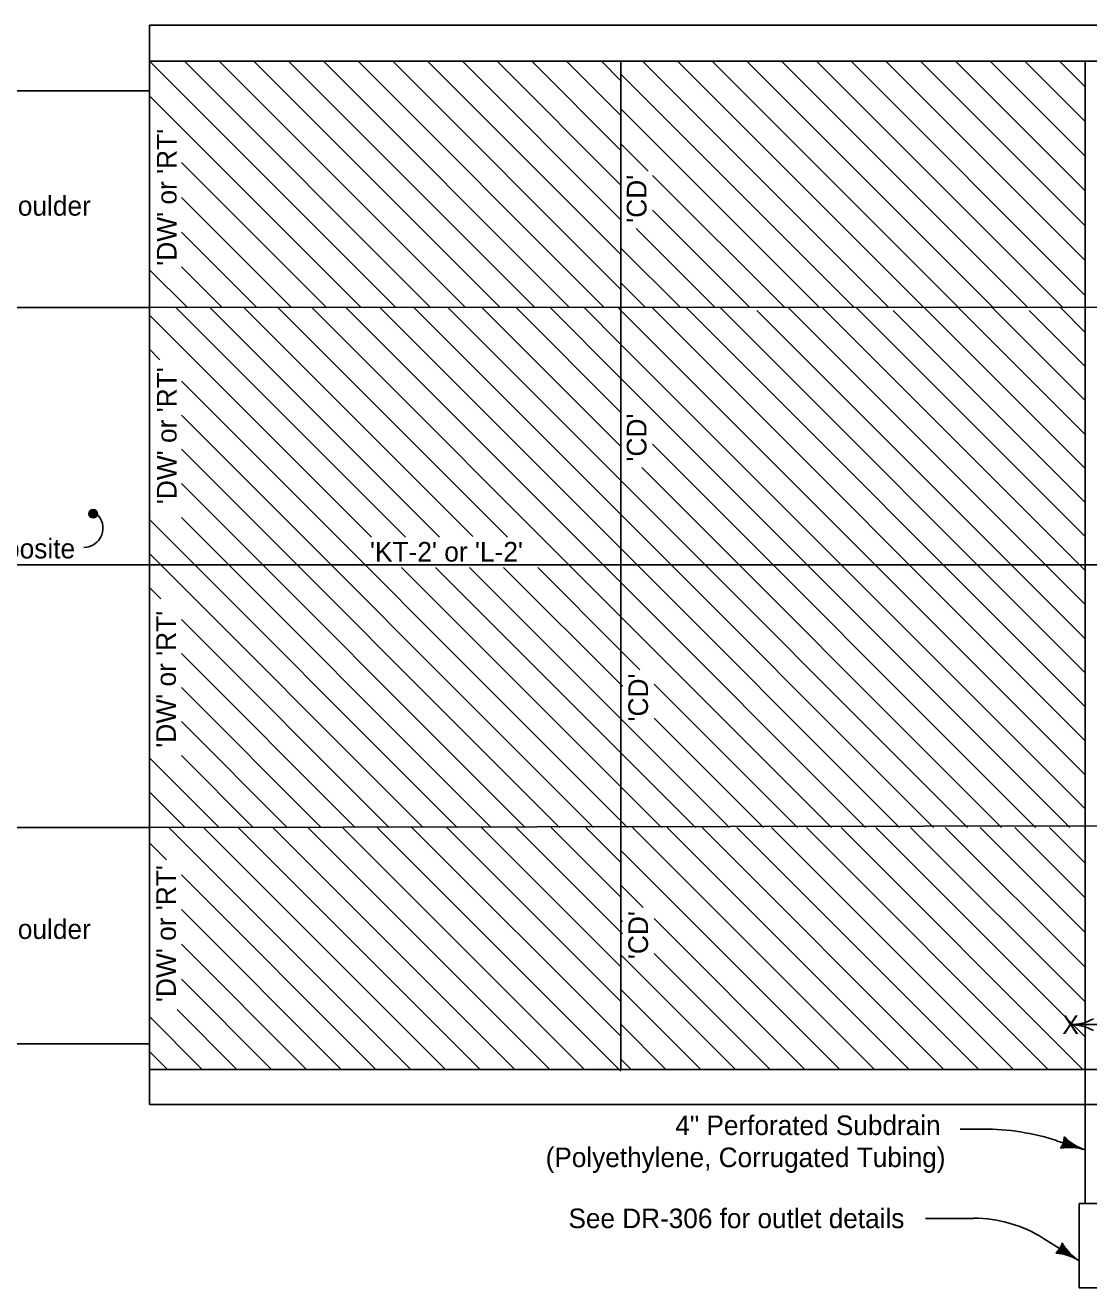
# Model space of a CAD drawing. Extents: x 9234 to 81668, y 5635 to 15999.
# Drawn here: x 24175 to 25088, y 5673 to 6757 of the extents above; entities that cross this region are included whole.
import ezdxf

# ---------------------------------------------------------------- set-up
doc = ezdxf.new("R2010")
doc.units = 0
doc.layers.add('PS_BOLT', color=7, linetype='Continuous')
doc.layers.add('PS_DIM', color=7, linetype='Continuous')

msp = doc.modelspace()

# ---------------------------------------------------------------- linework, layer by layer
msp.add_line((25828.3, 6726.2), (24281.5, 6726.2))
at = {"layer": 'PS_BOLT'}
for p, q in [((24281.5, 6562.1), (24281.5, 6603.8)), ((24281.5, 6514.6), (24281.5, 6068.3)), ((24750.3, 6068.3), (24686.4, 6132.3)), ((24721.1, 6068.3), (24686.4, 6103.1)), ((26267.5, 6071.6), (24281.5, 6068.3)), ((24691.9, 6068.3), (24686.4, 6073.9)), ((25072.2, 5898.9), (25103.5, 5898.9)), ((24977.8, 5809.2), (24997.5, 5809.2)), ((24947.8, 5732.6), (24989.3, 5732.6)), ((25049.4, 5715.4), (25079.9, 5696.2))]:
    msp.add_line(p, q, dxfattribs=at)
for centre, radius, start, end in [((24225, 6325.2), 16.5, 270, 48.6908), ((24997.5, 5603.7), 205.6, 72.1406, 90), ((24989.3, 5619.6), 113.1, 57.9168, 90)]:
    msp.add_arc(centre, radius, start, end, dxfattribs=at)
at = {"layer": 'PS_DIM'}
for p, q in [((26204.1, 6757), (24281.5, 6757)), ((24281.5, 6757), (24281.5, 6700.7)), ((24281.5, 6514.6), (24281.5, 6726.2)), ((24493.1, 6514.6), (24281.5, 6726.1)), ((24522.9, 6514.6), (24311.4, 6726.1)), ((24552.8, 6514.6), (24341.2, 6726.1)), ((24582.6, 6514.6), (24371.1, 6726.1)), ((24612.5, 6514.6), (24400.9, 6726.1)), ((24642.3, 6514.6), (24430.8, 6726.1)), ((24672.1, 6514.6), (24460.6, 6726.1)), ((24686.4, 6530.2), (24490.5, 6726.1)), ((24686.4, 6560.1), (24520.3, 6726.1)), ((24686.4, 6589.9), (24550.2, 6726.1)), ((24686.4, 6619.8), (24580, 6726.1)), ((24686.4, 6649.6), (24609.9, 6726.1)), ((24686.4, 6679.5), (24639.7, 6726.1)), ((24686.4, 6709.3), (24669.6, 6726.1)), ((24686.4, 6726.1), (24686.4, 6068.3)), ((24916.5, 6514.6), (24705, 6726.1)), ((24946.4, 6514.6), (24734.8, 6726.1)), ((24976.2, 6514.6), (24764.6, 6726.2)), ((25006.1, 6514.6), (24794.5, 6726.2)), ((25035.9, 6514.6), (24824.3, 6726.2)), ((25065.8, 6514.6), (24854.2, 6726.2)), ((25085.1, 6525.1), (24884, 6726.2)), ((25085.1, 6555), (24913.9, 6726.2)), ((25085.1, 6584.8), (24943.7, 6726.2)), ((25085.1, 6614.7), (24973.6, 6726.2)), ((25085.1, 6644.5), (25003.4, 6726.2)), ((25085.1, 6674.4), (25033.3, 6726.2)), ((25085.1, 6704.2), (25063.1, 6726.2)), ((25085.1, 6726.2), (25085.1, 6515.7)), ((24886.7, 6514.6), (24686.4, 6714.9)), ((24281.5, 6700.6), (24020.1, 6700.6)), ((24281.5, 6514.6), (24281.5, 6700.6)), ((25085.1, 6515.7), (25085.1, 6700.7)), ((24463.2, 6514.6), (24281.5, 6696.4)), ((24856.8, 6514.6), (24686.4, 6685.1)), ((24709.8, 6631.8), (24686.4, 6655.2)), ((24433.4, 6514.6), (24308.9, 6639.1)), ((24827, 6514.6), (24713.6, 6628)), ((24403.5, 6514.6), (24308.9, 6609.2)), ((24797.1, 6514.6), (24713.6, 6598.1)), ((24767.3, 6514.6), (24699.5, 6582.4)), ((24373.7, 6514.6), (24308.9, 6579.4)), ((24737.4, 6514.6), (24686.4, 6565.7)), ((24343.8, 6514.6), (24308.9, 6549.5)), ((24314, 6514.6), (24281.5, 6547.1)), ((24707.6, 6514.6), (24686.4, 6535.8)), ((24281.5, 6514.6), (26314.2, 6515.7)), ((25085.1, 6071.6), (25085.1, 6515.7)), ((24281.5, 6514.6), (23985.1, 6514.6)), ((24472, 6317.4), (24281.5, 6508)), ((24501.2, 6317.4), (24304.1, 6514.6)), ((24530.4, 6317.4), (24333.3, 6514.6)), ((24559.1, 6318), (24362.5, 6514.6)), ((24588.9, 6317.4), (24391.7, 6514.6)), ((24686.4, 6249.2), (24420.9, 6514.6)), ((24686.4, 6278.4), (24450.2, 6514.6)), ((24686.4, 6307.6), (24479.4, 6514.6)), ((24686.4, 6336.8), (24508.6, 6514.6)), ((24686.4, 6366.1), (24537.8, 6514.6)), ((24686.4, 6395.3), (24567, 6514.6)), ((24686.4, 6424.5), (24596.3, 6514.6)), ((24686.4, 6453.7), (24625.5, 6514.6)), ((24686.4, 6482.9), (24654.7, 6514.6)), ((24686.4, 6512.2), (24683.9, 6514.6)), ((25085.1, 6113.5), (24686.4, 6512.2)), ((25085.1, 6142.7), (24713.1, 6514.6)), ((25085.1, 6171.9), (24742.4, 6514.6)), ((25085.1, 6201.1), (24771.6, 6514.6)), ((25085.1, 6230.3), (24803.2, 6512.2)), ((25085.1, 6259.6), (24830, 6514.6)), ((25085.1, 6288.8), (24859.2, 6514.6)), ((25085.1, 6318), (24888.4, 6514.6)), ((25085.1, 6347.2), (24920.1, 6512.2)), ((25085.1, 6376.4), (24946.9, 6514.6)), ((25085.1, 6405.6), (24976.1, 6514.6)), ((25085.1, 6434.9), (25005.3, 6514.6)), ((25085.1, 6464.1), (25037, 6512.2)), ((25085.1, 6493.3), (25063.8, 6514.6)), ((25085.1, 6084.2), (24686.4, 6482.9)), ((24290.4, 6469.8), (24281.5, 6478.8)), ((24686.4, 6073.9), (24308.9, 6451.3)), ((25071.8, 6068.3), (24686.4, 6453.7)), ((24662.7, 6068.3), (24308.9, 6422.1)), ((24686.4, 6424.5), (24686.4, 6424.5)), ((25042.5, 6068.3), (24713.6, 6397.2)), ((24633.5, 6068.3), (24308.9, 6392.9)), ((24686.4, 6395.3), (24686.4, 6395.3)), ((25013.3, 6068.3), (24704.3, 6377.3)), ((24604.2, 6068.3), (24308.9, 6363.6)), ((24984.1, 6068.3), (24686.4, 6366.1)), ((24545.8, 6068.3), (24281.5, 6332.7)), ((24575, 6068.3), (24308.9, 6334.4)), ((24954.9, 6068.3), (24686.4, 6336.8)), ((24516.6, 6068.3), (24281.5, 6303.4)), ((24925.7, 6068.3), (24686.4, 6307.6)), ((25828.3, 6293.7), (23947.1, 6293.7)), ((24686.4, 6103.1), (24498, 6291.5)), ((24686.4, 6132.3), (24527.2, 6291.5)), ((24687.8, 6160.1), (24556.4, 6291.5)), ((24687.8, 6189.4), (24585.6, 6291.5)), ((24686.4, 6220), (24614.9, 6291.5)), ((24896.4, 6068.3), (24686.4, 6278.4)), ((24291.3, 6264.4), (24281.5, 6274.2)), ((24487.4, 6068.3), (24308.9, 6246.8)), ((24867.2, 6068.3), (24686.4, 6249.2)), ((24458.1, 6068.3), (24308.9, 6217.5)), ((24702.7, 6203.6), (24686.4, 6220)), ((24687.8, 6189.4), (24686.4, 6190.7)), ((24838, 6068.3), (24715, 6191.3)), ((24428.9, 6068.3), (24308.9, 6188.3)), ((24399.7, 6068.3), (24308.9, 6159.1)), ((24779.6, 6068.3), (24686.4, 6161.5)), ((24808.8, 6068.3), (24715, 6162.1)), ((24341.3, 6068.3), (24281.5, 6128.1)), ((24370.5, 6068.3), (24308.9, 6129.9)), ((24312, 6068.3), (24281.5, 6098.9)), ((25085.1, 6071.6), (25085.1, 5861.1)), ((24281.5, 6068.3), (23985.1, 6068.3)), ((24281.5, 5861.1), (24281.5, 6068.3)), ((24505.2, 5861.1), (24298, 6068.3)), ((24535, 5861.1), (24327.9, 6068.3)), ((24564.9, 5861.1), (24357.7, 6068.3)), ((24594.7, 5861.1), (24387.5, 6068.3)), ((24624.6, 5861.1), (24417.4, 6068.3)), ((24654.4, 5861.1), (24447.2, 6068.3)), ((24686.4, 5859), (24477.1, 6068.3)), ((24686.4, 5888.9), (24506.9, 6068.3)), ((24686.4, 5918.7), (24536.8, 6068.3)), ((24686.4, 5948.6), (24566.6, 6068.3)), ((24687.8, 5977), (24596.5, 6068.3)), ((24686.4, 6008.3), (24626.3, 6068.3)), ((24686.4, 6038.1), (24656.2, 6068.3)), ((24686.4, 6068.3), (24686.4, 5861.1)), ((24903.5, 5861.1), (24696.3, 6068.3)), ((24933.4, 5861.1), (24726.2, 6068.3)), ((24963.2, 5861.1), (24756, 6068.3)), ((24993.1, 5861.1), (24785.9, 6068.3)), ((25022.9, 5861.1), (24815.7, 6068.3)), ((25052.8, 5861.1), (24845.6, 6068.3)), ((25082.6, 5861.1), (24875.4, 6068.3)), ((25085.1, 5888.5), (24905.3, 6068.3)), ((25085.1, 5918.4), (24935.1, 6068.3)), ((25085.1, 5948.2), (24964.9, 6068.3)), ((25085.1, 5978.1), (24994.8, 6068.3)), ((25085.1, 6007.9), (25024.6, 6068.3)), ((25085.1, 6037.7), (25054.5, 6068.3)), ((24296.2, 6040.3), (24281.5, 6055)), ((24873.7, 5861.1), (24686.4, 6048.4)), ((24475.3, 5861.1), (24308.9, 6027.6)), ((24705.4, 5999.5), (24686.4, 6018.6)), ((24445.5, 5861.1), (24308.9, 5997.7)), ((24687.8, 5987.4), (24686.4, 5988.8)), ((24843.8, 5861.1), (24715, 5990)), ((24415.7, 5861.1), (24308.9, 5967.9)), ((24784.1, 5861.1), (24686.4, 5958.9)), ((24814, 5861.1), (24715, 5960.1)), ((24385.8, 5861.1), (24308.9, 5938)), ((24754.3, 5861.1), (24686.4, 5929.1)), ((24356, 5861.1), (24305.1, 5912)), ((24326.1, 5861.1), (24281.5, 5905.8)), ((24724.4, 5861.1), (24686.4, 5899.2)), ((24281.5, 5882.4), (24020.1, 5882.4)), ((24281.5, 5830.3), (24281.5, 5882.4)), ((24296.3, 5861.1), (24281.5, 5875.9)), ((24694.6, 5861.1), (24686.4, 5869.4)), ((26118.6, 5860.4), (24281.5, 5860.4)), ((25085.1, 5861.1), (25085.1, 5745.4)), ((25791.3, 5830.3), (24281.5, 5830.3)), ((25060.5, 5799.3), (25085.1, 5791.4)), ((25085.1, 5791.4), (25066.3, 5797.5)), ((25096.4, 5745.4), (25079.9, 5745.4)), ((25079.9, 5745.4), (25079.9, 5673)), ((25079.9, 5696.2), (25063.2, 5706.7)), ((25096.4, 5673), (25079.9, 5673))]:
    msp.add_line(p, q, dxfattribs=at)
for points in [[(24233.4, 6334.3), (24232.2, 6334.9), (24230.3, 6335.5), (24229.9, 6337.4), (24230.2, 6339.1), (24231.4, 6340.6), (24233.2, 6340.5), (24235.1, 6340.2), (24236, 6338.7), (24236.2, 6337.1), (24235.1, 6335), (24233.7, 6334.8), (24231.8, 6335.3), (24230.2, 6336.5), (24230.3, 6338.3), (24231.5, 6339.8), (24233.2, 6339.9), (24235.1, 6339.6), (24235.4, 6338.5), (24235.8, 6337.2), (24234.9, 6335.7), (24233.5, 6335.7), (24231.9, 6335.9), (24230.8, 6336.8), (24231.4, 6338.4), (24232.5, 6339.3), (24234.1, 6339.4), (24234.5, 6338.5), (24235.1, 6337.6), (24234.3, 6336.3), (24233.1, 6336), (24232, 6336.6), (24232, 6337.8), (24232.5, 6338.6), (24233.6, 6338.9), (24234.1, 6338.4), (24234.4, 6337.8), (24233.9, 6336.8), (24233.1, 6336.7), (24232.4, 6337.1), (24232.5, 6337.7), (24233, 6338.1), (24233.8, 6338.1), (24233.8, 6337.6), (24233.1, 6337.3)], [(25065.5, 5793.9), (25067.4, 5797.1), (25067.8, 5800.9), (25071.3, 5797.5), (25077.5, 5793.9), (25069.8, 5794.5), (25066.3, 5794.1), (25068, 5796.9), (25068.4, 5799.3), (25070.8, 5797.1), (25074.2, 5794.9), (25069.9, 5795.1), (25067.6, 5795), (25068.9, 5797.9), (25071.3, 5795.9), (25068.9, 5795.9), (25069.2, 5796.9), (25070.1, 5796.3)], [(25061.6, 5703.4), (25064.2, 5706.1), (25065.5, 5709.6), (25068.1, 5705.5), (25073.2, 5700.4), (25065.9, 5703), (25062.4, 5703.4), (25064.7, 5705.7), (25065.7, 5707.9), (25067.5, 5705.2), (25070.2, 5702.3), (25066.1, 5703.5), (25063.9, 5704), (25065.9, 5706.5), (25067.7, 5703.9), (25065.4, 5704.5), (25065.9, 5705.4), (25066.7, 5704.6)]]:
    msp.add_lwpolyline(points, dxfattribs=at)
msp.add_circle((24233.1, 6337.6), 3.62, dxfattribs=at)
for centre, radius, start, end in [((25072.2, 5941.2), 42.3, 270, 298.0725), ((25072.2, 5856.6), 42.3, 61.9275, 90), ((25050.2, 5802.7), 16.9, 324.4082, 359.8749), ((25098.5, 5833), 43.7, 224.0691, 252.1415), ((25071.7, 5749.8), 43.7, 72.1415, 100.214), ((25048.9, 5715.7), 16.9, 310.1825, 345.6492), ((25056.7, 5659.2), 43.7, 57.9159, 85.9884), ((25103.1, 5733.2), 43.7, 209.8434, 237.9159)]:
    msp.add_arc(centre, radius, start, end, dxfattribs=at)

# ---------------------------------------------------------------- texts
at = {"layer": 'PS_BOLT'}
for s, height, p in [("'DW' or 'RT'", 16.884, (24304.7, 6550.5)), ("'CD'", 16.88, (24708.3, 6587.4)), ("'DW' or 'RT'", 16.884, (24304.7, 6345.8)), ("'CD'", 16.88, (24708.3, 6382.4)), ("'DW' or 'RT'", 16.884, (24304.1, 6136.7)), ("'CD'", 16.88, (24709.6, 6159.2)), ("'DW' or 'RT'", 16.884, (24304.1, 5918.3)), ("'CD'", 16.88, (24709.6, 5955.2))]:
    msp.add_text(s, height=height, rotation=90, dxfattribs=at).set_placement(p)
for s, height, p in [('Existing Shoulder', 16.884, (24055.4, 6593.5)), ('P.C.C. or Composite', 16.884, (24010.6, 6299.2)), ("'KT-2' or 'L-2'", 16.884, (24470.8, 6296.5)), ('Existing Shoulder', 16.884, (24055.4, 5972.5)), ('X', 16, (25065.4, 5890.9)), ('4" Perforated Subdrain ', 16.8, (24733.1, 5804.1)), ('(Polyethylene, Corrugated Tubing)', 16.8, (24621.7, 5776.6)), ('See DR-306 for outlet details', 16.8, (24641.3, 5724.2))]:
    msp.add_text(s, height=height, dxfattribs=at).set_placement(p)

doc.saveas('drawing.dxf')
